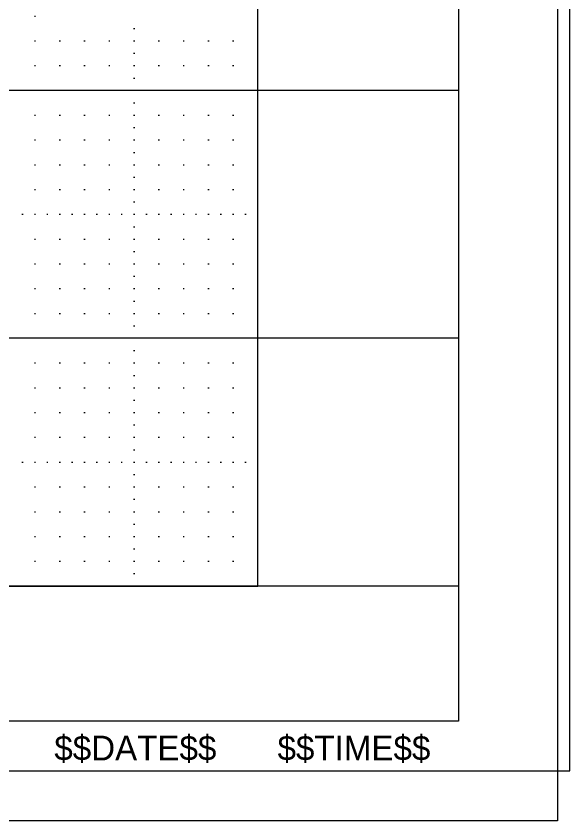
# Model space of a CAD drawing. Extents: x -3.6 to 32.1, y -0.4 to 25.6.
# Drawn here: x 29.832 to 32.067, y -0.403 to 2.845 of the extents above; entities that cross this region are included whole.
import ezdxf

# ---------------------------------------------------------------- set-up
doc = ezdxf.new("R2010")
doc.units = 0
for name, color, linetype in [('Level 4', 7, 'Continuous'), ('Level 48', 7, 'Continuous'), ('Level 5', 7, 'Continuous'), ('Level 62', 7, 'Continuous'), ('Level 63', 7, 'Continuous'), ('Level 63 Full', 7, 'Continuous'), ('R_Border Prem', 7, 'Continuous')]:
    doc.layers.add(name, color=color, linetype=linetype)

msp = doc.modelspace()

# ---------------------------------------------------------------- linework, layer by layer
at = {"layer": 'Level 4'}
for p, q in [((30.808, 0.545), (30.808, 19.545)), ((31.617, 2.545), (-0.001, 2.545)), ((31.617, 1.545), (-0.001, 1.545)), ((31.617, 0.545), (-0.001, 0.545))]:
    msp.add_line(p, q, dxfattribs=at)
at = {"layer": 'Level 5'}
for p, q in [((29.9055, 2.845), (29.9105, 2.845)), ((30.3055, 2.795), (30.3105, 2.795)), ((29.9055, 2.745), (29.9105, 2.745)), ((30.0055, 2.745), (30.0105, 2.745)), ((30.1055, 2.745), (30.1105, 2.745)), ((30.2055, 2.745), (30.2105, 2.745)), ((30.3055, 2.745), (30.3105, 2.745)), ((30.4055, 2.745), (30.4105, 2.745)), ((30.5055, 2.745), (30.5105, 2.745)), ((30.6055, 2.745), (30.6105, 2.745)), ((30.7055, 2.745), (30.7105, 2.745)), ((30.3055, 2.695), (30.3105, 2.695)), ((29.9055, 2.645), (29.9105, 2.645)), ((30.0055, 2.645), (30.0105, 2.645)), ((30.1055, 2.645), (30.1105, 2.645)), ((30.2055, 2.645), (30.2105, 2.645)), ((30.3055, 2.645), (30.3105, 2.645)), ((30.4055, 2.645), (30.4105, 2.645)), ((30.5055, 2.645), (30.5105, 2.645)), ((30.6055, 2.645), (30.6105, 2.645)), ((30.7055, 2.645), (30.7105, 2.645)), ((30.3055, 2.595), (30.3105, 2.595)), ((30.3055, 2.495), (30.3105, 2.495)), ((29.9055, 2.445), (29.9105, 2.445)), ((30.0055, 2.445), (30.0105, 2.445)), ((30.1055, 2.445), (30.1105, 2.445)), ((30.2055, 2.445), (30.2105, 2.445)), ((30.3055, 2.445), (30.3105, 2.445)), ((30.4055, 2.445), (30.4105, 2.445)), ((30.5055, 2.445), (30.5105, 2.445)), ((30.6055, 2.445), (30.6105, 2.445)), ((30.7055, 2.445), (30.7105, 2.445)), ((30.3055, 2.395), (30.3105, 2.395)), ((29.9055, 2.345), (29.9105, 2.345)), ((30.0055, 2.345), (30.0105, 2.345)), ((30.1055, 2.345), (30.1105, 2.345)), ((30.2055, 2.345), (30.2105, 2.345)), ((30.3055, 2.345), (30.3105, 2.345)), ((30.4055, 2.345), (30.4105, 2.345)), ((30.5055, 2.345), (30.5105, 2.345)), ((30.6055, 2.345), (30.6105, 2.345)), ((30.7055, 2.345), (30.7105, 2.345)), ((30.3055, 2.295), (30.3105, 2.295)), ((29.9055, 2.245), (29.9105, 2.245)), ((30.0055, 2.245), (30.0105, 2.245)), ((30.1055, 2.245), (30.1105, 2.245)), ((30.2055, 2.245), (30.2105, 2.245)), ((30.3055, 2.245), (30.3105, 2.245)), ((30.4055, 2.245), (30.4105, 2.245)), ((30.5055, 2.245), (30.5105, 2.245)), ((30.6055, 2.245), (30.6105, 2.245)), ((30.7055, 2.245), (30.7105, 2.245)), ((30.3055, 2.195), (30.3105, 2.195)), ((29.9055, 2.145), (29.9105, 2.145)), ((30.0055, 2.145), (30.0105, 2.145)), ((30.1055, 2.145), (30.1105, 2.145)), ((30.2055, 2.145), (30.2105, 2.145)), ((30.3055, 2.145), (30.3105, 2.145)), ((30.4055, 2.145), (30.4105, 2.145)), ((30.5055, 2.145), (30.5105, 2.145)), ((30.6055, 2.145), (30.6105, 2.145)), ((30.7055, 2.145), (30.7105, 2.145)), ((30.3055, 2.095), (30.3105, 2.095)), ((29.8555, 2.045), (29.8605, 2.045)), ((29.9055, 2.045), (29.9105, 2.045)), ((29.9555, 2.045), (29.9605, 2.045)), ((30.0055, 2.045), (30.0105, 2.045)), ((30.0555, 2.045), (30.0605, 2.045)), ((30.1055, 2.045), (30.1105, 2.045)), ((30.1555, 2.045), (30.1605, 2.045)), ((30.2055, 2.045), (30.2105, 2.045)), ((30.2555, 2.045), (30.2605, 2.045)), ((30.3055, 2.045), (30.3105, 2.045)), ((30.3555, 2.045), (30.3605, 2.045)), ((30.4055, 2.045), (30.4105, 2.045)), ((30.4555, 2.045), (30.4605, 2.045)), ((30.5055, 2.045), (30.5105, 2.045)), ((30.5555, 2.045), (30.5605, 2.045)), ((30.6055, 2.045), (30.6105, 2.045)), ((30.6555, 2.045), (30.6605, 2.045)), ((30.7055, 2.045), (30.7105, 2.045)), ((30.7555, 2.045), (30.7605, 2.045)), ((30.3055, 1.995), (30.3105, 1.995)), ((29.9055, 1.945), (29.9105, 1.945)), ((30.0055, 1.945), (30.0105, 1.945)), ((30.1055, 1.945), (30.1105, 1.945)), ((30.2055, 1.945), (30.2105, 1.945)), ((30.3055, 1.945), (30.3105, 1.945)), ((30.4055, 1.945), (30.4105, 1.945)), ((30.5055, 1.945), (30.5105, 1.945)), ((30.6055, 1.945), (30.6105, 1.945)), ((30.7055, 1.945), (30.7105, 1.945)), ((30.3055, 1.895), (30.3105, 1.895)), ((29.9055, 1.845), (29.9105, 1.845)), ((30.0055, 1.845), (30.0105, 1.845)), ((30.1055, 1.845), (30.1105, 1.845)), ((30.2055, 1.845), (30.2105, 1.845)), ((30.3055, 1.845), (30.3105, 1.845)), ((30.4055, 1.845), (30.4105, 1.845)), ((30.5055, 1.845), (30.5105, 1.845)), ((30.6055, 1.845), (30.6105, 1.845)), ((30.7055, 1.845), (30.7105, 1.845)), ((30.3055, 1.795), (30.3105, 1.795)), ((29.9055, 1.745), (29.9105, 1.745)), ((30.0055, 1.745), (30.0105, 1.745)), ((30.1055, 1.745), (30.1105, 1.745)), ((30.2055, 1.745), (30.2105, 1.745)), ((30.3055, 1.745), (30.3105, 1.745)), ((30.4055, 1.745), (30.4105, 1.745)), ((30.5055, 1.745), (30.5105, 1.745)), ((30.6055, 1.745), (30.6105, 1.745)), ((30.7055, 1.745), (30.7105, 1.745)), ((30.3055, 1.695), (30.3105, 1.695)), ((29.9055, 1.645), (29.9105, 1.645)), ((30.0055, 1.645), (30.0105, 1.645)), ((30.1055, 1.645), (30.1105, 1.645)), ((30.2055, 1.645), (30.2105, 1.645)), ((30.3055, 1.645), (30.3105, 1.645)), ((30.4055, 1.645), (30.4105, 1.645)), ((30.5055, 1.645), (30.5105, 1.645)), ((30.6055, 1.645), (30.6105, 1.645)), ((30.7055, 1.645), (30.7105, 1.645)), ((30.3055, 1.595), (30.3105, 1.595)), ((30.3055, 1.495), (30.3105, 1.495)), ((29.9055, 1.445), (29.9105, 1.445)), ((30.0055, 1.445), (30.0105, 1.445)), ((30.1055, 1.445), (30.1105, 1.445)), ((30.2055, 1.445), (30.2105, 1.445)), ((30.3055, 1.445), (30.3105, 1.445)), ((30.4055, 1.445), (30.4105, 1.445)), ((30.5055, 1.445), (30.5105, 1.445)), ((30.6055, 1.445), (30.6105, 1.445)), ((30.7055, 1.445), (30.7105, 1.445)), ((30.3055, 1.395), (30.3105, 1.395)), ((29.9055, 1.345), (29.9105, 1.345)), ((30.0055, 1.345), (30.0105, 1.345)), ((30.1055, 1.345), (30.1105, 1.345)), ((30.2055, 1.345), (30.2105, 1.345)), ((30.3055, 1.345), (30.3105, 1.345)), ((30.4055, 1.345), (30.4105, 1.345)), ((30.5055, 1.345), (30.5105, 1.345)), ((30.6055, 1.345), (30.6105, 1.345)), ((30.7055, 1.345), (30.7105, 1.345)), ((30.3055, 1.295), (30.3105, 1.295)), ((29.9055, 1.245), (29.9105, 1.245)), ((30.0055, 1.245), (30.0105, 1.245)), ((30.1055, 1.245), (30.1105, 1.245)), ((30.2055, 1.245), (30.2105, 1.245)), ((30.3055, 1.245), (30.3105, 1.245)), ((30.4055, 1.245), (30.4105, 1.245)), ((30.5055, 1.245), (30.5105, 1.245)), ((30.6055, 1.245), (30.6105, 1.245)), ((30.7055, 1.245), (30.7105, 1.245)), ((30.3055, 1.195), (30.3105, 1.195)), ((29.9055, 1.145), (29.9105, 1.145)), ((30.0055, 1.145), (30.0105, 1.145)), ((30.1055, 1.145), (30.1105, 1.145)), ((30.2055, 1.145), (30.2105, 1.145)), ((30.3055, 1.145), (30.3105, 1.145)), ((30.4055, 1.145), (30.4105, 1.145)), ((30.5055, 1.145), (30.5105, 1.145)), ((30.6055, 1.145), (30.6105, 1.145)), ((30.7055, 1.145), (30.7105, 1.145)), ((30.3055, 1.095), (30.3105, 1.095)), ((29.8555, 1.045), (29.8605, 1.045)), ((29.9055, 1.045), (29.9105, 1.045)), ((29.9555, 1.045), (29.9605, 1.045)), ((30.0055, 1.045), (30.0105, 1.045)), ((30.0555, 1.045), (30.0605, 1.045)), ((30.1055, 1.045), (30.1105, 1.045)), ((30.1555, 1.045), (30.1605, 1.045)), ((30.2055, 1.045), (30.2105, 1.045)), ((30.2555, 1.045), (30.2605, 1.045)), ((30.3055, 1.045), (30.3105, 1.045)), ((30.3555, 1.045), (30.3605, 1.045)), ((30.4055, 1.045), (30.4105, 1.045)), ((30.4555, 1.045), (30.4605, 1.045)), ((30.5055, 1.045), (30.5105, 1.045)), ((30.5555, 1.045), (30.5605, 1.045)), ((30.6055, 1.045), (30.6105, 1.045)), ((30.6555, 1.045), (30.6605, 1.045)), ((30.7055, 1.045), (30.7105, 1.045)), ((30.7555, 1.045), (30.7605, 1.045)), ((30.3055, 0.995), (30.3105, 0.995)), ((29.9055, 0.945), (29.9105, 0.945)), ((30.0055, 0.945), (30.0105, 0.945)), ((30.1055, 0.945), (30.1105, 0.945)), ((30.2055, 0.945), (30.2105, 0.945)), ((30.3055, 0.945), (30.3105, 0.945)), ((30.4055, 0.945), (30.4105, 0.945)), ((30.5055, 0.945), (30.5105, 0.945)), ((30.6055, 0.945), (30.6105, 0.945)), ((30.7055, 0.945), (30.7105, 0.945)), ((30.3055, 0.895), (30.3105, 0.895)), ((29.9055, 0.845), (29.9105, 0.845)), ((30.0055, 0.845), (30.0105, 0.845)), ((30.1055, 0.845), (30.1105, 0.845)), ((30.2055, 0.845), (30.2105, 0.845)), ((30.3055, 0.845), (30.3105, 0.845)), ((30.4055, 0.845), (30.4105, 0.845)), ((30.5055, 0.845), (30.5105, 0.845)), ((30.6055, 0.845), (30.6105, 0.845)), ((30.7055, 0.845), (30.7105, 0.845)), ((30.3055, 0.795), (30.3105, 0.795)), ((29.9055, 0.745), (29.9105, 0.745)), ((30.0055, 0.745), (30.0105, 0.745)), ((30.1055, 0.745), (30.1105, 0.745)), ((30.2055, 0.745), (30.2105, 0.745)), ((30.3055, 0.745), (30.3105, 0.745)), ((30.4055, 0.745), (30.4105, 0.745)), ((30.5055, 0.745), (30.5105, 0.745)), ((30.6055, 0.745), (30.6105, 0.745)), ((30.7055, 0.745), (30.7105, 0.745)), ((30.3055, 0.695), (30.3105, 0.695)), ((29.9055, 0.645), (29.9105, 0.645)), ((30.0055, 0.645), (30.0105, 0.645)), ((30.1055, 0.645), (30.1105, 0.645)), ((30.2055, 0.645), (30.2105, 0.645)), ((30.3055, 0.645), (30.3105, 0.645)), ((30.4055, 0.645), (30.4105, 0.645)), ((30.5055, 0.645), (30.5105, 0.645)), ((30.6055, 0.645), (30.6105, 0.645)), ((30.7055, 0.645), (30.7105, 0.645)), ((30.3055, 0.595), (30.3105, 0.595))]:
    msp.add_line(p, q, dxfattribs=at)
at = {"layer": 'Level 62'}
for p, q in [((30.808, 0.545), (30.8075, 19.5579)), ((0.808, 0.545), (30.808, 0.545)), ((30.808, 0.545), (30.808, 0.545)), ((30.808, 0.545), (30.808, 0.545))]:
    msp.add_line(p, q, dxfattribs=at)
at = {"layer": 'Level 63'}
msp.add_lwpolyline([(-1.263, -0.2005), (32.067, -0.2005), (32.067, 20.7465), (-1.263, 20.7465)], close=True, dxfattribs=at)
at = {"layer": 'Level 63 Full'}
msp.add_lwpolyline([(32.017, -0.403), (-3.583, -0.403), (-3.583, 20.947), (32.017, 20.947)], close=True, dxfattribs=at)
at = {"layer": 'R_Border Prem'}
for p, q in [((31.617, 20.545), (31.617, -0.001)), ((31.617, -0.001), (-0.001, -0.001))]:
    msp.add_line(p, q, dxfattribs=at)

# ---------------------------------------------------------------- texts
at = {"layer": 'Level 48'}
for s, p in [('$$DATE$$', (29.986, -0.159)), ('$$TIME$$', (30.887, -0.159))]:
    msp.add_text(s, height=0.1, dxfattribs=at).set_placement(p)

doc.saveas('drawing.dxf')
